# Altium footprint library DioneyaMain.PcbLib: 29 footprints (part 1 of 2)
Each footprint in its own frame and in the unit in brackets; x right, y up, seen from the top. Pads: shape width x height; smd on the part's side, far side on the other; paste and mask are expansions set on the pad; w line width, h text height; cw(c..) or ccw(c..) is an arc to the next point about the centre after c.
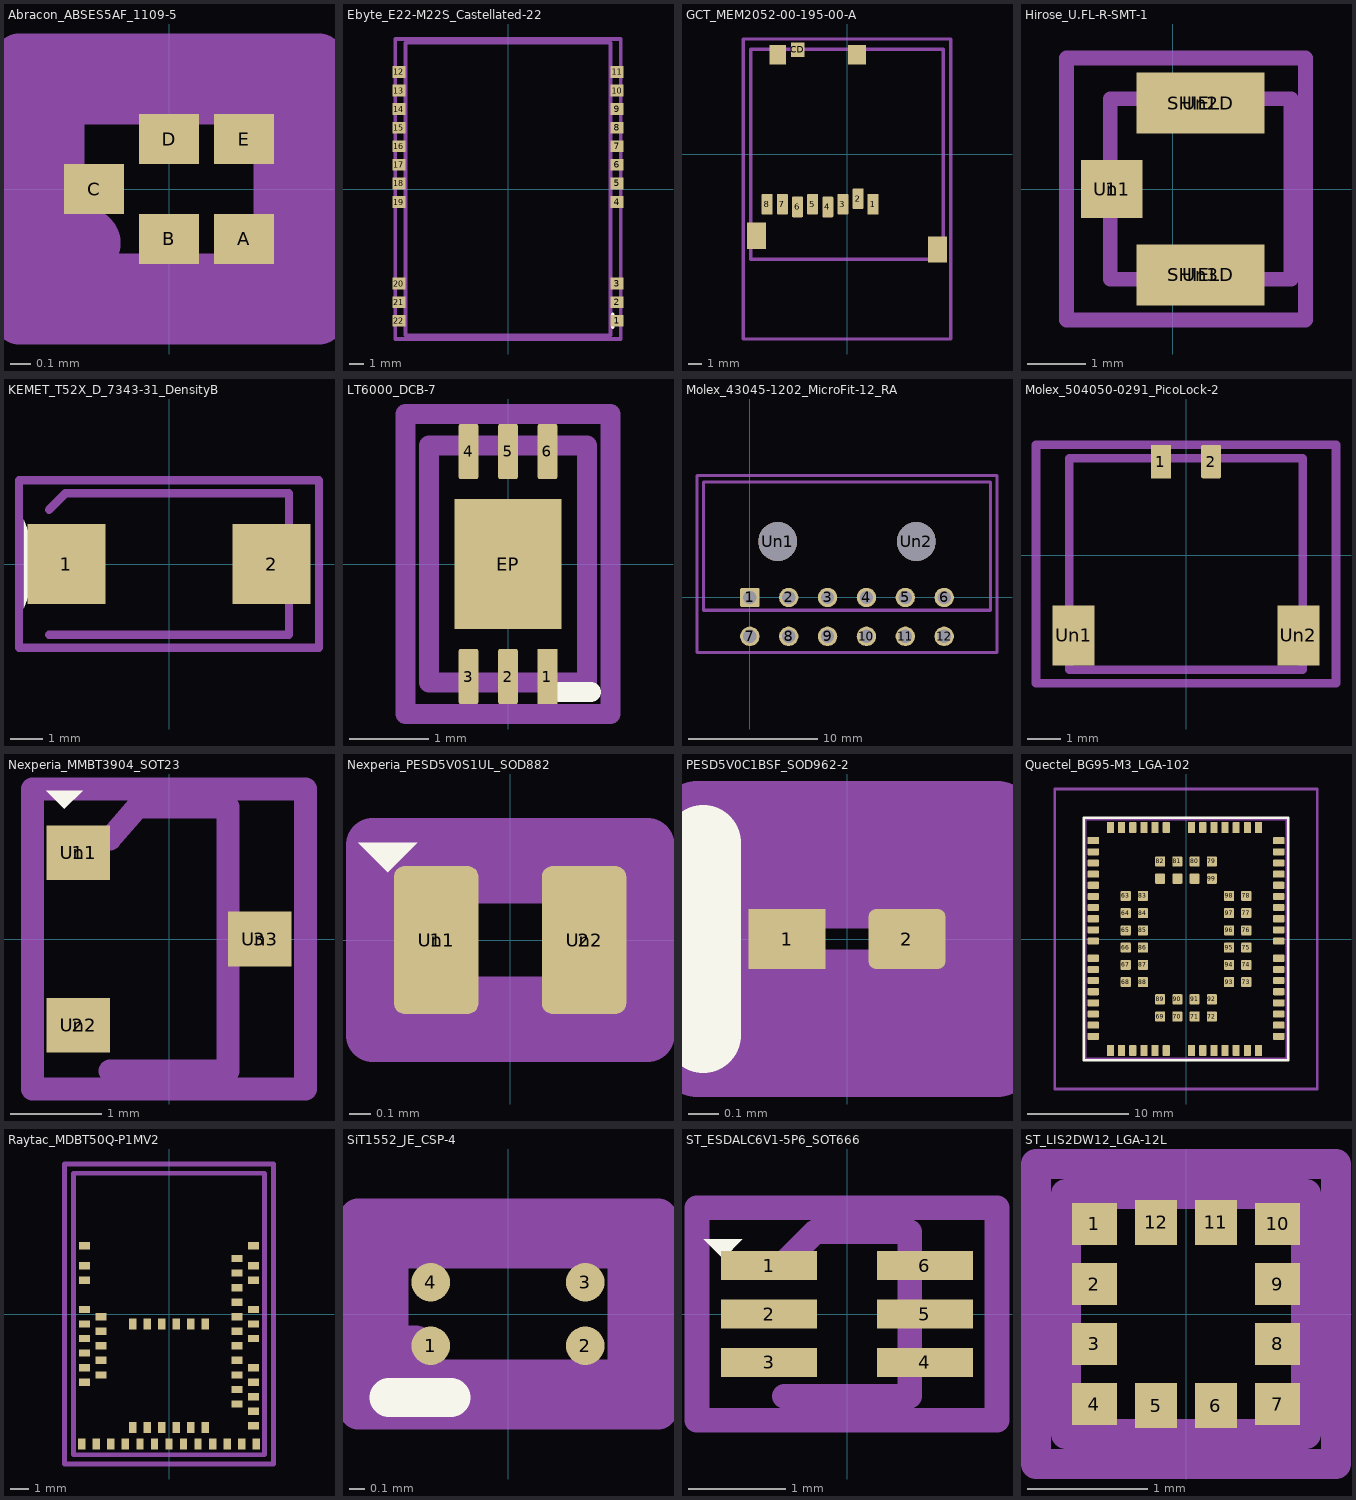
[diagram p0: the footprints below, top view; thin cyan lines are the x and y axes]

## Abracon_ABSES5AF_1109-5 [mm]
pads (5):
  rect 0.3x0.25 smd: A(0.375,-0.25) B(0,-0.25) C(-0.375,0) D(0,0.25) E(0.375,0.25)
F.Fab:
  circle w0.254: c-0.42,-0.27 r0.05
  region: -0.382,-0.232 -0.366,-0.27 -0.382,-0.308 -0.42,-0.324 -0.458,-0.308 -0.474,-0.27 -0.458,-0.232 -0.42,-0.216
  lines w0.254: -0.55,-0.45 -0.55,0.45 0.55,0.45 0.55,-0.45 -0.55,-0.45
F.CrtYd:
  lines w0.254: -0.75,-0.65 -0.75,0.65 0.75,0.65 0.75,-0.65 -0.75,-0.65

## Ebyte_E22-M22S_Castellated-22 [mm]
pads (22):
  rect 0.9x0.8 smd: 1(7.45,-9) 2(7.45,-7.73) 3(7.45,-6.46) 4(7.45,-0.89) 5(7.45,0.38) 6(7.45,1.65) 7(7.45,2.92) 8(7.45,4.19) 9(7.45,5.46) 10(7.45,6.73) 11(7.45,8) 12(-7.45,8) 13(-7.45,6.73) 14(-7.45,5.46) 15(-7.45,4.19) 16(-7.45,2.92) 17(-7.45,1.65) 18(-7.45,0.38) 19(-7.45,-0.89) 20(-7.45,-6.46) 21(-7.45,-7.73) 22(-7.45,-9)
F.SilkS:
  lines w0.254: 7.15,-9.45 7.15,-8.55
F.Fab:
  lines w0.254: -7,-10 -7,10 7,10 7,-10 -7,-10
F.CrtYd:
  lines w0.254: -7.7,-10.25 -7.7,10.25 7.7,10.25 7.7,-10.25 -7.7,-10.25

## GCT_MEM2052-00-195-00-A [mm]
pads (13):
  rect 0.8x1.5 smd: 1(1.905,-3.635)
  rrect20% 0.8x1.5 smd: 2(0.805,-3.235) 3(-0.295,-3.635) 4(-1.395,-3.835) 5(-2.495,-3.635) 6(-3.595,-3.835) 7(-4.695,-3.635) 8(-5.795,-3.635)
  rect 1x1.04 smd: CD(-3.585,7.595)
  rect 1.4x1.9 smd: SHIELD(-6.575,-5.925) SHIELD(6.575,-6.925)
  rect 1.2x1.4 smd: SHIELD(-5.035,7.225)
  rect 1.3x1.4 smd: SHIELD(0.715,7.225)
F.Fab:
  lines w0.254: -7,-7.625 -7,7.625 7,7.625 7,-7.625 -7,-7.625
F.CrtYd:
  lines w0.254: -7.525,-13.425 -7.525,8.365 7.525,8.365 7.525,-13.425 -7.525,-13.425

## Hirose_U.FL-R-SMT-1 [mm]
pads (6):
  rect 1.05x1 smd: 1(-1.05,0)
  rect 2.2x1.05 smd: SHIELD(0.475,-1.475) SHIELD(0.475,1.475)
  rect 0.85x0.8 on Top Paste: Un1(-1.05,0)
  rect 2x0.9 on Top Paste: Un2(0.475,1.475) Un3(0.475,-1.475)
F.Fab:
  lines w0.254: -1.075,-1.55 -1.075,1.55 2.025,1.55 2.025,-1.55 -1.075,-1.55
F.CrtYd:
  lines w0.254: -1.825,-2.25 -1.825,2.25 2.275,2.25 2.275,-2.25 -1.825,-2.25

## KEMET_T52X_D_7343-31_DensityB [mm]
pads (2):
  rect 2.37x2.43 smd: 1(-3.12,0) 2(3.12,0)
F.SilkS:
  region: -3.92,0 -4.42,-1.35 -4.42,1.35
F.Fab:
  lines w0.254: -3.65,-2.15 3.65,-2.15 3.65,2.15 -3.15,2.15 -3.65,1.65
F.CrtYd:
  lines w0.254: -4.56,-2.55 -4.56,2.55 4.56,2.55 4.56,-2.55 -4.56,-2.55

## LT6000_DCB-7 [mm]
pads (7):
  rect 0.25x0.7 smd: 1(0.5,-1.425)
  rrect20% 0.25x0.7 smd: 2(0,-1.425) 3(-0.5,-1.425) 4(-0.5,1.425) 5(0,1.425) 6(0.5,1.425)
  rect 1.35x1.65 smd: EP(0,0)
F.SilkS:
  lines w0.254: 0.65,-1.62 1.05,-1.62
F.Fab:
  lines w0.254: -1,-1.5 -1,1.5 1,1.5 1,-1.5 -1,-1.5
F.CrtYd:
  lines w0.254: -1.3,-1.9 -1.3,1.9 1.3,1.9 1.3,-1.9 -1.3,-1.9

## Molex_43045-1202_MicroFit-12_RA [mm]
pads (14):
  rrect20% 1.5x1.5 hole 1.02: 1(0,0)
  round 1.5 hole 1.02: 2(3,0) 3(6,0) 4(9,0) 5(12,0) 6(15,0) 7(0,-3) 8(3,-3) 9(6,-3) 10(9,-3) 11(12,-3) 12(15,-3)
  round 3 hole 3: Un1(2.15,4.32) Un2(12.85,4.32)
F.Fab:
  lines w0.254: -3.575,-0.99 -3.575,8.92 18.575,8.92 18.575,-0.99 -3.575,-0.99
F.CrtYd:
  lines w0.254: -4.08,-4.25 -4.08,9.42 19.08,9.42 19.08,-4.25 -4.08,-4.25

## Molex_504050-0291_PicoLock-2 [mm]
pads (4):
  rect 0.6x1 smd: 1(-0.75,2.795)
  rrect20% 0.6x1 smd: 2(0.75,2.795)
  rect 1.25x1.8 smd: Un1(-3.355,-2.395) Un2(3.355,-2.395)
F.Fab:
  lines w0.254: -3.485,-3.425 -3.485,2.895 3.485,2.895 3.485,-3.425 -3.485,-3.425
F.CrtYd:
  lines w0.254: -4.48,-3.82 -4.48,3.3 4.48,3.3 4.48,-3.82 -4.48,-3.82

## Nexperia_MMBT3904_SOT23 [mm]
pads (6):
  rect 0.7x0.6 smd: 1(-1,0.95) 2(-1,-0.95) 3(1,0)
  rect 0.6x0.5 on Top Paste: Un1(-1,0.95) Un2(-1,-0.95) Un3(1,0)
F.SilkS:
  region: -1.15,1.43 -1.35,1.63 -0.95,1.63
F.Fab:
  lines w0.254: -0.65,-1.45 0.65,-1.45 0.65,1.45 -0.35,1.45 -0.65,1.1
F.CrtYd:
  lines w0.254: -1.5,-1.65 -1.5,1.65 1.5,1.65 1.5,-1.65 -1.5,-1.65

## Nexperia_PESD5V0S1UL_SOD882 [mm]
pads (4):
  rrect25% 0.4x0.7 smd: 1(-0.35,0) 2(0.35,0)
  rrect33% 0.3x0.6 on Top Paste: Un1(-0.35,0) Un2(0.35,0)
F.SilkS:
  region: -0.58,0.32 -0.72,0.46 -0.44,0.46
F.Fab:
  lines w0.254: -0.5,-0.3 0.5,-0.3 0.5,0.3 -0.5,0.3
F.CrtYd:
  lines w0.254: -0.65,-0.45 -0.65,0.45 0.65,0.45 0.65,-0.45 -0.65,-0.45

## PESD5V0C1BSF_SOD962-2 [mm]
pads (2):
  rect 0.256x0.2 smd: 1(-0.2,0)
  rrect25% 0.256x0.2 smd: 2(0.2,0)
F.SilkS:
  lines w0.254: -0.48,-0.32 -0.48,0.32
F.Fab:
  lines w0.254: -0.312,-0.162 -0.312,0.162 0.312,0.162 0.312,-0.162 -0.312,-0.162
F.CrtYd:
  lines w0.254: -0.5,-0.4 -0.5,0.4 0.5,0.4 0.5,-0.4 -0.5,-0.4

## Quectel_BG95-M3_LGA-102 [mm]
pads (102):
  rect 1.1x0.7 smd: 1(-9.15,9.7)
  rrect20% 1.1x0.7 smd: 2(-9.15,8.6) 3(-9.15,7.5) 4(-9.15,6.4) 5(-9.15,5.3) 6(-9.15,4.2) 7(-9.15,3.1) 8(-9.15,2) 9(-9.15,0.9) 10(-9.15,-0.2) 11(-9.15,-1.9) 12(-9.15,-3) 13(-9.15,-4.1) 14(-9.15,-5.2) 15(-9.15,-6.3) 16(-9.15,-7.4) 17(-9.15,-8.5) 18(-9.15,-9.6) 32(9.15,-9.6) 33(9.15,-8.5) 34(9.15,-7.4) 35(9.15,-6.3) 36(9.15,-5.2) 37(9.15,-4.1) 38(9.15,-3) 39(9.15,-1.9) 40(9.15,-0.2) 41(9.15,0.9) 42(9.15,2) 43(9.15,3.1) 44(9.15,4.2) 45(9.15,5.3) 46(9.15,6.4) 47(9.15,7.5) 48(9.15,8.6) 49(9.15,9.7)
  rrect20% 0.7x1.1 smd: 19(-7.45,-11) 20(-6.35,-11) 21(-5.25,-11) 22(-4.15,-11) 23(-3.05,-11) 24(-1.95,-11) 25(0.55,-11) 26(1.65,-11) 27(2.75,-11) 28(3.85,-11) 29(4.95,-11) 30(6.05,-11) 31(7.15,-11) 50(7.15,11) 51(6.05,11) 52(4.95,11) 53(3.85,11) 54(2.75,11) 55(1.65,11) 56(0.55,11) 57(-1.95,11) 58(-3.05,11) 59(-4.15,11) 60(-5.25,11) 61(-6.35,11) 62(-7.45,11)
  rrect20% 1x1 smd: 63(-5.95,4.25) 64(-5.95,2.55) 65(-5.95,0.85) 66(-5.95,-0.85) 67(-5.95,-2.55) 68(-5.95,-4.25) 69(-2.55,-7.65) 70(-0.85,-7.65) 71(0.85,-7.65) 72(2.55,-7.65) 73(5.95,-4.25) 74(5.95,-2.55) 75(5.95,-0.85) 76(5.95,0.85) 77(5.95,2.55) 78(5.95,4.25) 79(2.55,7.65) 80(0.85,7.65) 81(-0.85,7.65) 82(-2.55,7.65) 83(-4.25,4.25) 84(-4.25,2.55) 85(-4.25,0.85) 86(-4.25,-0.85) 87(-4.25,-2.55) 88(-4.25,-4.25) 89(-2.55,-5.95) 90(-0.85,-5.95) 91(0.85,-5.95) 92(2.55,-5.95) 93(4.25,-4.25) 94(4.25,-2.55) 95(4.25,-0.85) 96(4.25,0.85) 97(4.25,2.55) 98(4.25,4.25) 99(2.55,5.95) 100(0.85,5.95) 101(-0.85,5.95) 102(-2.55,5.95)
F.SilkS:
  lines w0.254: -10.1,-11.95 -10.1,11.95 10.1,11.95 10.1,-11.95 -10.1,-11.95
F.Fab:
  lines w0.254: -9.95,-11.8 -9.95,11.8 9.95,11.8 9.95,-11.8 -9.95,-11.8
F.CrtYd:
  lines w0.254: -12.95,-14.8 -12.95,14.8 12.95,14.8 12.95,-14.8 -12.95,-14.8

## Raytac_MDBT50Q-P1MV2 [mm]
pads (61):
  rect 0.6x0.4 smd: 1(-4.65,3.75) 2(-4.65,2.65) 3(-4.65,1.85) 4(-4.65,0.25) 5(-3.75,-0.15) 6(-4.65,-0.55) 7(-3.75,-0.95) 8(-4.65,-1.35) 9(-3.75,-1.75) 10(-4.65,-2.15) 11(-3.75,-2.55) 12(-4.65,-2.95) 13(-3.75,-3.35) 14(-4.65,-3.75) 34(4.65,-6.15) 35(4.65,-5.35) 36(3.75,-4.95) 37(4.65,-4.55) 38(3.75,-4.15) 39(4.65,-3.75) 40(3.75,-3.35) 41(4.65,-2.95) 42(3.75,-2.55) 43(3.75,-1.75) 44(4.65,-1.35) 45(3.75,-0.95) 46(4.65,-0.55) 47(3.75,-0.15) 48(4.65,0.25) 49(3.75,0.65) 50(3.75,1.45) 51(4.65,1.85) 52(3.75,2.25) 53(4.65,2.65) 54(3.75,3.05) 55(4.65,3.75)
  rect 0.4x0.6 smd: 15(-4.8,-7.15) 16(-4,-7.15) 17(-3.2,-7.15) 18(-2.4,-7.15) 19(-2,-6.25) 20(-1.6,-7.15) 21(-1.2,-6.25) 22(-0.8,-7.15) 23(-0.4,-6.25) 24(0,-7.15) 25(0.4,-6.25) 26(0.8,-7.15) 27(1.2,-6.25) 28(1.6,-7.15) 29(2,-6.25) 30(2.4,-7.15) 31(3.2,-7.15) 32(4,-7.15) 33(4.8,-7.15) 56(-2,-0.55) 57(-1.2,-0.55) 58(-0.4,-0.55) 59(0.4,-0.55) 60(1.2,-0.55) 61(2,-0.55)
F.Fab:
  lines w0.254: -5.25,-7.75 -5.25,7.75 5.25,7.75 5.25,-7.75 -5.25,-7.75
F.CrtYd:
  lines w0.254: -5.75,-8.25 -5.75,8.25 5.75,8.25 5.75,-8.25 -5.75,-8.25

## SiT1552_JE_CSP-4 [mm]
pads (4):
  round 0.25 smd: 1(-0.5,-0.205) 2(0.5,-0.205) 3(0.5,0.205) 4(-0.5,0.205)
F.SilkS:
  lines w0.254: -0.77,-0.54 -0.37,-0.54
F.Fab:
  circle w0.254: c-0.61,-0.25 r0.05
  region: -0.572,-0.212 -0.556,-0.25 -0.572,-0.288 -0.61,-0.304 -0.648,-0.288 -0.664,-0.25 -0.648,-0.212 -0.61,-0.196
  lines w0.254: -0.77,-0.42 -0.77,0.42 0.77,0.42 0.77,-0.42 -0.77,-0.42
F.CrtYd:
  lines w0.254: -0.97,-0.62 -0.97,0.62 0.97,0.62 0.97,-0.62 -0.97,-0.62

## ST_ESDALC6V1-5P6_SOT666 [mm]
pads (6):
  rect 0.99x0.3 smd: 1(-0.805,0.5) 2(-0.805,0) 3(-0.805,-0.5) 4(0.805,-0.5) 5(0.805,0) 6(0.805,0.5)
F.SilkS:
  region: -1.28,0.57 -1.48,0.77 -1.08,0.77
F.Fab:
  lines w0.254: -0.65,-0.85 0.65,-0.85 0.65,0.85 -0.33,0.85 -0.65,0.53
F.CrtYd:
  lines w0.254: -1.55,-1.1 -1.55,1.1 1.55,1.1 1.55,-1.1 -1.55,-1.1

## ST_LIS2DW12_LGA-12L [mm]
pads (12):
  rect 0.375x0.35 smd: 1(-0.763,0.75) 2(-0.763,0.25) 3(-0.763,-0.25) 4(-0.763,-0.75) 7(0.763,-0.75) 8(0.763,-0.25) 9(0.763,0.25) 10(0.763,0.75)
  rect 0.35x0.375 smd: 5(-0.25,-0.763) 6(0.25,-0.763) 11(0.25,0.763) 12(-0.25,0.763)
F.Fab:
  lines w0.254: -1,-1 -1,1 1,1 1,-1 -1,-1
F.CrtYd:
  lines w0.254: -1.25,-1.25 -1.25,1.25 1.25,1.25 1.25,-1.25 -1.25,-1.25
